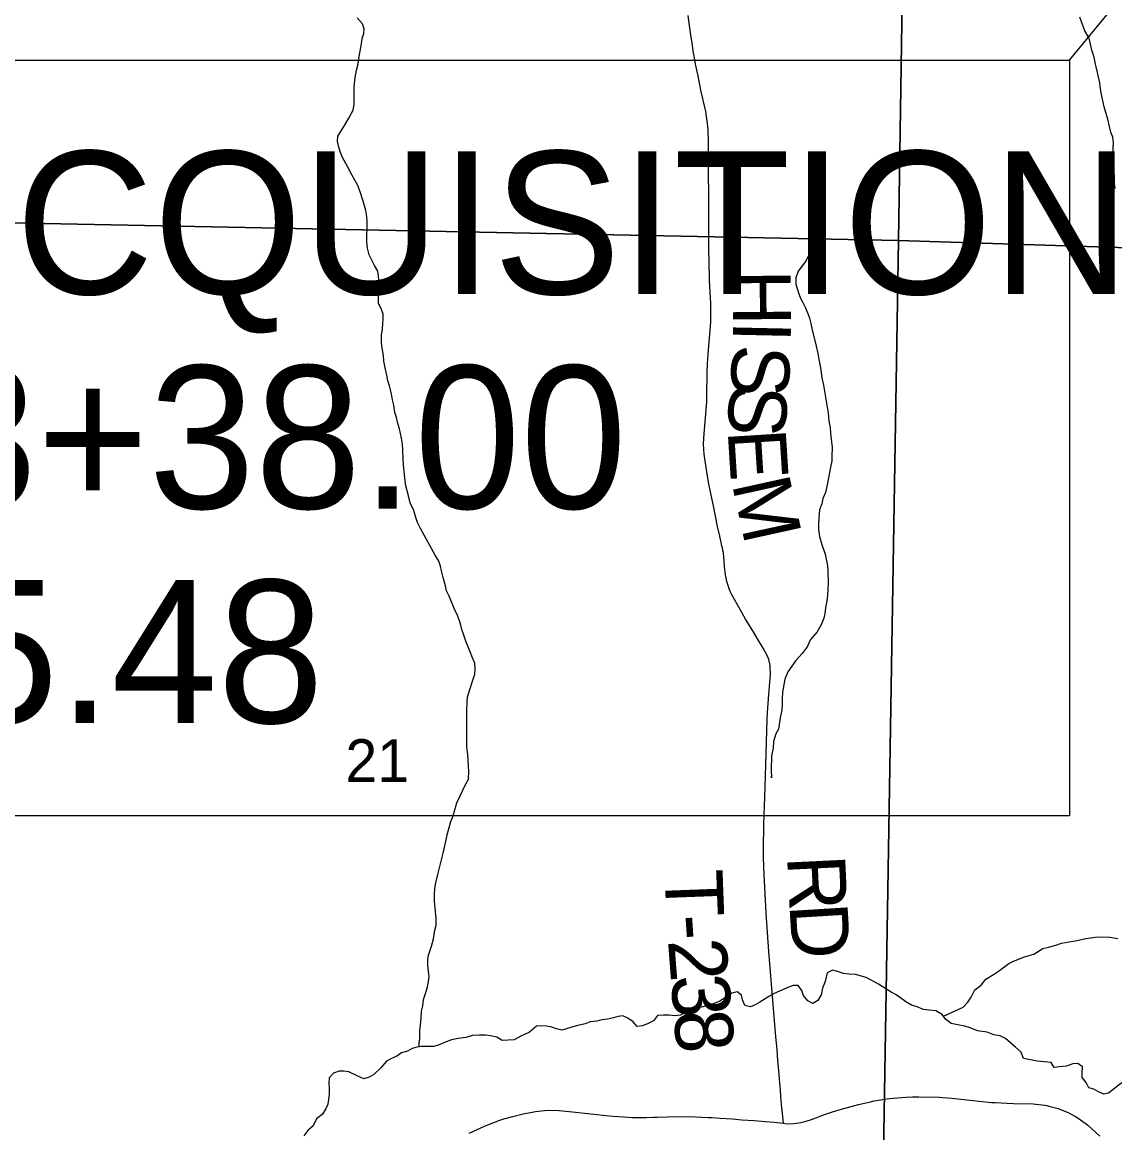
# Model space of a CAD drawing. Extents: x 0 to 34, y 0 to 22.
# Drawn here: x 11.571 to 12.641, y 15.132 to 16.22 of the extents above; entities that cross this region are included whole.
import ezdxf

# ---------------------------------------------------------------- set-up
doc = ezdxf.new("R2010")
doc.units = 0
for name, color, linetype in [('GM_X_Corporation', 7, 'Continuous'), ('GM_X_County_Road', 7, 'Continuous'), ('GM_X_Minor_River', 7, 'Continuous'), ('GM_X_Section_Text', 7, 'Continuous'), ('GM_X_Township_Road', 7, 'Continuous'), ('GM_X_Township_Road_Text', 7, 'Continuous'), ('SH_Text', 7, 'Continuous')]:
    doc.layers.add(name, color=color, linetype=linetype)

msp = doc.modelspace()

# ---------------------------------------------------------------- linework, layer by layer
at = {"layer": 'GM_X_Corporation'}
for points in [[(11.4395, 17.0255), (12.4446, 17.0089), (12.4291, 16.0062), (11.4274, 16.0262)], [(12.4446, 17.0089), (13.4493, 16.9912), (13.4336, 15.974), (12.4291, 16.0062)], [(11.4274, 16.0262), (12.4291, 16.0062), (12.4126, 14.9928), (11.4045, 15.0097)], [(12.4291, 16.0062), (13.4336, 15.974), (13.4208, 14.9679), (12.4126, 14.9928)]]:
    msp.add_lwpolyline(points, close=True, dxfattribs=at)
at = {"layer": 'GM_X_County_Road'}
msp.add_lwpolyline([(12.0086, 15.1317), (12.0114, 15.1331), (12.0235, 15.1387), (12.0267, 15.14), (12.0387, 15.1446), (12.0425, 15.1459), (12.0512, 15.1482), (12.0614, 15.1507), (12.0704, 15.1525), (12.0734, 15.153), (12.0823, 15.1541), (12.0853, 15.1542), (12.0966, 15.154), (12.1099, 15.1527), (12.1457, 15.1487), (12.1495, 15.1484), (12.1599, 15.1477), (12.1685, 15.1472), (12.1819, 15.1473), (12.1893, 15.1474), (12.1928, 15.1476), (12.2028, 15.1479), (12.2123, 15.1482), (12.2304, 15.1479), (12.243, 15.1473), (12.2466, 15.1471), (12.2545, 15.1465), (12.2664, 15.1457), (12.2757, 15.145), (12.2877, 15.1441), (12.2986, 15.1432), (12.3077, 15.1425), (12.3164, 15.1415), (12.3183, 15.1414), (12.3237, 15.1411), (12.3292, 15.1415), (12.3334, 15.1422), (12.3387, 15.1436), (12.3439, 15.1453), (12.3576, 15.1503), (12.3647, 15.1527), (12.372, 15.1549), (12.39, 15.1598), (12.4017, 15.1626), (12.4055, 15.1635), (12.4203, 15.1657), (12.4244, 15.1662), (12.4364, 15.1671), (12.4428, 15.1673), (12.449, 15.1675), (12.4694, 15.167), (12.4723, 15.1669), (12.4815, 15.1661), (12.4961, 15.1646), (12.5203, 15.1619), (12.5235, 15.1617), (12.542, 15.1609), (12.5611, 15.1605), (12.5637, 15.1602), (12.5726, 15.1591), (12.5745, 15.1589), (12.5767, 15.1584), (12.5856, 15.1559), (12.5879, 15.155), (12.5954, 15.1521), (12.5978, 15.1509), (12.6028, 15.1483), (12.6044, 15.1472), (12.6132, 15.141), (12.6147, 15.1398), (12.6266, 15.129)], dxfattribs=at)
at = {"layer": 'GM_X_Minor_River'}
for points in [[(11.9226, 15.9135), (11.9237, 15.9196), (11.9241, 15.9246), (11.9244, 15.9291), (11.9244, 15.9341), (11.9225, 15.9386), (11.9198, 15.9447), (11.9198, 15.9492), (11.9202, 15.9587), (11.9205, 15.9633), (11.9197, 15.9716), (11.919, 15.9762), (11.9159, 15.9815), (11.9106, 15.9921), (11.909, 15.9986), (11.9082, 16.0047), (11.9082, 16.01), (11.9086, 16.0191), (11.9086, 16.0244), (11.9082, 16.0297), (11.9074, 16.0354), (11.9047, 16.0445), (11.9016, 16.0537), (11.8993, 16.0601), (11.8936, 16.0704), (11.8894, 16.0787), (11.8844, 16.0874), (11.8825, 16.0924), (11.8806, 16.0984), (11.8794, 16.1034), (11.8798, 16.1083), (11.8855, 16.117), (11.8908, 16.1258), (11.8949, 16.1338), (11.896, 16.1395), (11.896, 16.1562), (11.8967, 16.1657), (11.8982, 16.1729), (11.8997, 16.1793), (11.9008, 16.1862), (11.903, 16.1987), (11.9038, 16.204), (11.9053, 16.209), (11.9056, 16.2135), (11.9041, 16.2185), (11.8988, 16.2242)], [(12.6416, 16.0571), (12.6408, 16.0624), (12.6408, 16.067), (12.6404, 16.0749), (12.64, 16.0799), (12.6396, 16.0909), (12.6395, 16.0962), (12.6399, 16.1023), (12.6391, 16.1072), (12.6372, 16.1121), (12.6361, 16.1178), (12.6345, 16.125), (12.6307, 16.1372), (12.6284, 16.1474), (12.6272, 16.1547), (12.6264, 16.1607), (12.6241, 16.1706), (12.6222, 16.1789), (12.621, 16.1858), (12.6187, 16.1926), (12.616, 16.2044), (12.6118, 16.2116), (12.6068, 16.2249)], [(12.3508, 16.0555), (12.3493, 16.0509), (12.3481, 16.0463), (12.347, 16.0403), (12.347, 16.0353), (12.3482, 16.03), (12.3497, 16.0236), (12.3497, 16.019), (12.3494, 16.0133), (12.3483, 16.0084), (12.3456, 16.0031), (12.3434, 15.9977), (12.3415, 15.992), (12.3388, 15.9867), (12.3351, 15.9818), (12.3309, 15.9761), (12.3287, 15.9696), (12.3287, 15.9635), (12.3314, 15.9548), (12.3329, 15.9502), (12.3356, 15.9453), (12.3379, 15.9408), (12.3405, 15.9347), (12.3421, 15.9301), (12.3432, 15.9248), (12.3448, 15.9187), (12.3486, 15.9028), (12.3502, 15.8956), (12.3513, 15.8895), (12.3529, 15.8815), (12.354, 15.8717), (12.3556, 15.8645), (12.3602, 15.8371), (12.361, 15.8295), (12.3622, 15.8231), (12.3626, 15.817), (12.3637, 15.809), (12.3641, 15.8033), (12.3638, 15.795), (12.3638, 15.7904), (12.3627, 15.784), (12.3608, 15.7737), (12.3593, 15.7669), (12.3578, 15.7593), (12.3552, 15.7536), (12.3541, 15.7482), (12.3518, 15.7422), (12.3507, 15.7293), (12.3507, 15.7232), (12.3519, 15.7163), (12.3542, 15.7084), (12.3573, 15.6989), (12.3584, 15.694), (12.3596, 15.6875), (12.36, 15.6822), (12.3604, 15.6708), (12.36, 15.6643), (12.3593, 15.6552), (12.3578, 15.6465), (12.3571, 15.6408), (12.356, 15.6362), (12.3533, 15.6298), (12.3496, 15.6229), (12.3431, 15.6153), (12.3397, 15.6081), (12.3348, 15.6016), (12.3288, 15.5948), (12.3246, 15.5891), (12.3208, 15.5838), (12.3178, 15.5765), (12.3156, 15.5636), (12.3152, 15.5572), (12.3152, 15.5515), (12.3149, 15.5465), (12.3134, 15.5385), (12.3115, 15.5275), (12.3089, 15.523), (12.3066, 15.5154), (12.3063, 15.5089), (12.3048, 15.5013), (12.3044, 15.4873), (12.3048, 15.48), (12.3047, 15.4816)], [(11.9594, 15.2164), (11.9594, 15.2197), (11.9602, 15.2246), (11.9601, 15.2326), (11.9609, 15.2375), (11.9616, 15.2444), (11.962, 15.2512), (11.9631, 15.2565), (11.9638, 15.2626), (11.9665, 15.2706), (11.9676, 15.2752), (11.9687, 15.2805), (11.9695, 15.2854), (11.9687, 15.2904), (11.9679, 15.2964), (11.9679, 15.3017), (11.9686, 15.3063), (11.9717, 15.315), (11.9735, 15.3223), (11.975, 15.3306), (11.9761, 15.3356), (11.9761, 15.3424), (11.9757, 15.3485), (11.9745, 15.3591), (11.9745, 15.3656), (11.9749, 15.3713), (11.976, 15.377), (11.9779, 15.3853), (11.9801, 15.3944), (11.9831, 15.4062), (11.985, 15.4146), (11.9872, 15.4252), (11.9906, 15.437), (11.9929, 15.4427), (11.9944, 15.4484), (11.9966, 15.4552), (11.9993, 15.4617), (12.0042, 15.472), (12.0079, 15.4784), (12.0083, 15.486), (12.0079, 15.4913), (12.0071, 15.5027), (12.0063, 15.51), (12.0063, 15.5191), (12.0062, 15.546), (12.0066, 15.554), (12.0069, 15.559), (12.0096, 15.5673), (12.0118, 15.5745), (12.0141, 15.5814), (12.0144, 15.5867), (12.014, 15.592), (12.0117, 15.5973), (12.0094, 15.6034), (12.0075, 15.6083), (12.0052, 15.6136), (12.0029, 15.6205), (12.0014, 15.625), (12.0002, 15.6307), (11.9972, 15.6391), (11.9945, 15.644), (11.9918, 15.6505), (11.9888, 15.6577), (11.9865, 15.663), (11.9853, 15.6679), (11.983, 15.6759), (11.9815, 15.6827), (11.9803, 15.6873), (11.9788, 15.6922), (11.9753, 15.6979), (11.97, 15.7074), (11.9665, 15.7139), (11.9608, 15.7241), (11.9578, 15.7298), (11.9562, 15.7347), (11.9543, 15.7416), (11.9509, 15.7491), (11.9493, 15.7548), (11.9466, 15.7659), (11.9455, 15.7734), (11.9443, 15.7867), (11.9439, 15.7917), (11.9435, 15.8008), (11.9431, 15.8065), (11.9423, 15.8126), (11.9404, 15.8217), (11.9388, 15.827), (11.9373, 15.8327), (11.9358, 15.8376), (11.9346, 15.8448), (11.9334, 15.8501), (11.9323, 15.8558), (11.9304, 15.8638), (11.9288, 15.8687), (11.928, 15.8741), (11.9261, 15.8813), (11.925, 15.8881), (11.9246, 15.8934), (11.923, 15.9025), (11.9226, 15.9071), (11.9226, 15.9135)], [(12.4732, 15.2465), (12.4927, 15.2551), (12.4973, 15.2601), (12.5003, 15.265), (12.5041, 15.2722), (12.5101, 15.2768), (12.5147, 15.2825), (12.5223, 15.2871), (12.5272, 15.2905), (12.5374, 15.2981), (12.542, 15.3004), (12.5526, 15.3046), (12.5617, 15.3073), (12.5708, 15.3126), (12.5761, 15.3141), (12.5833, 15.316), (12.589, 15.3179), (12.5962, 15.3191), (12.6026, 15.3203), (12.6129, 15.3225), (12.622, 15.3237), (12.6292, 15.3241), (12.6364, 15.3237), (12.644, 15.3226)], [(12.516, 15.2309), (12.5065, 15.232), (12.4993, 15.235), (12.4943, 15.2365), (12.4875, 15.238), (12.481, 15.2391), (12.4757, 15.2433), (12.4719, 15.2479), (12.4658, 15.2516), (12.459, 15.2524), (12.4536, 15.2531), (12.4476, 15.2554), (12.4419, 15.2573), (12.4365, 15.2603), (12.4316, 15.2641), (12.427, 15.2672), (12.4221, 15.2698), (12.4168, 15.2732), (12.4095, 15.2778), (12.4031, 15.2815), (12.3977, 15.2842), (12.3871, 15.2872), (12.381, 15.2876), (12.3753, 15.2883), (12.3696, 15.2902), (12.3647, 15.2914), (12.3594, 15.2887), (12.3575, 15.2803), (12.3549, 15.2739), (12.3534, 15.2674), (12.3503, 15.2617), (12.3454, 15.2587), (12.3405, 15.2613), (12.3363, 15.2666), (12.3344, 15.2716), (12.3309, 15.2765), (12.326, 15.2765), (12.3207, 15.2746), (12.3074, 15.2685), (12.3021, 15.2658), (12.2934, 15.2601), (12.2889, 15.2574), (12.2843, 15.2555), (12.2786, 15.257), (12.2763, 15.2623), (12.2755, 15.2669), (12.271, 15.2703), (12.266, 15.2688), (12.2588, 15.2642), (12.2543, 15.2612), (12.2471, 15.2581), (12.2418, 15.257), (12.2365, 15.2551), (12.2308, 15.2554), (12.2247, 15.2532), (12.2202, 15.2501), (12.2156, 15.2474), (12.2099, 15.2467), (12.2042, 15.2474), (12.1989, 15.2474), (12.1932, 15.247), (12.1891, 15.2417), (12.1834, 15.239), (12.1781, 15.2371), (12.1731, 15.2364), (12.1693, 15.2409), (12.164, 15.2443), (12.159, 15.2466), (12.1545, 15.2462), (12.1499, 15.2447), (12.1442, 15.2435), (12.1389, 15.2428), (12.1336, 15.2416), (12.1272, 15.2408), (12.1222, 15.2389), (12.115, 15.2374)], [(12.115, 15.2374), (12.1093, 15.2355), (12.104, 15.234), (12.0995, 15.2328), (12.0942, 15.234), (12.0896, 15.2355), (12.0843, 15.2366), (12.0793, 15.237), (12.0744, 15.2366), (12.0676, 15.2309), (12.0593, 15.2267), (12.0528, 15.2233), (12.0467, 15.2229), (12.041, 15.2225), (12.0357, 15.2259), (12.0296, 15.227), (12.0247, 15.2278), (12.0186, 15.2278), (12.0118, 15.2274), (12.0053, 15.2255), (11.9978, 15.2247), (11.9913, 15.2232), (11.9845, 15.2205), (11.9792, 15.2182), (11.9739, 15.2167), (11.9617, 15.2167), (11.9572, 15.2159), (11.9526, 15.2147), (11.9481, 15.2121), (11.9424, 15.2105), (11.9378, 15.2071), (11.9325, 15.2048), (11.9276, 15.2022), (11.9219, 15.1957), (11.9151, 15.1892), (11.9106, 15.1866), (11.9052, 15.185), (11.8995, 15.1877), (11.8908, 15.1919), (11.8859, 15.1926), (11.8813, 15.1926), (11.8756, 15.1907), (11.8715, 15.1861), (11.8711, 15.1808), (11.8715, 15.1755), (11.8715, 15.1705), (11.8708, 15.1648), (11.87, 15.1603), (11.8681, 15.1557), (11.8644, 15.15), (11.859, 15.1458), (11.8557, 15.139), (11.8504, 15.1344), (11.8466, 15.1291)], [(12.6156, 15.1763), (12.613, 15.1816), (12.6092, 15.1862), (12.6091, 15.1907), (12.6095, 15.1968), (12.6049, 15.2002), (12.6, 15.1998), (12.5935, 15.1975), (12.5871, 15.1968), (12.5818, 15.196), (12.5787, 15.2009), (12.5723, 15.2017), (12.5651, 15.2024), (12.5571, 15.2039), (12.5518, 15.2051), (12.5495, 15.2111), (12.5438, 15.2161), (12.5342, 15.2244), (12.5289, 15.2271), (12.5228, 15.2282), (12.516, 15.2309)], [(12.7092, 15.1301), (12.7035, 15.1347), (12.6981, 15.1388), (12.6932, 15.1392), (12.6887, 15.1385), (12.6822, 15.1381), (12.6784, 15.1426), (12.6734, 15.1502), (12.6708, 15.1548), (12.6662, 15.1578), (12.6628, 15.1623), (12.6616, 15.1673), (12.6604, 15.1726), (12.6604, 15.1771), (12.657, 15.1825), (12.6509, 15.1832), (12.6456, 15.179), (12.635, 15.171), (12.6305, 15.1699), (12.6251, 15.1722), (12.6206, 15.1748), (12.6156, 15.1763)]]:
    msp.add_lwpolyline(points, dxfattribs=at)
at = {"layer": 'GM_X_Township_Road'}
msp.add_lwpolyline([(12.3164, 15.1415), (12.3155, 15.151), (12.3147, 15.1598), (12.3141, 15.1677), (12.3136, 15.174), (12.313, 15.1812), (12.3123, 15.1888), (12.3117, 15.1963), (12.3111, 15.2028), (12.3102, 15.2137), (12.3091, 15.2262), (12.3023, 15.3099), (12.3002, 15.3378), (12.2996, 15.3475), (12.2977, 15.385), (12.2971, 15.4014), (12.2969, 15.4102), (12.2972, 15.4342), (12.2982, 15.461), (12.2992, 15.4925), (12.3006, 15.5374), (12.3009, 15.5439), (12.3022, 15.5614), (12.3039, 15.5809), (12.3036, 15.5885), (12.3034, 15.5903), (12.3022, 15.5956), (12.3015, 15.5974), (12.2998, 15.6011), (12.2967, 15.6069), (12.2921, 15.6145), (12.2864, 15.6237), (12.2794, 15.6354), (12.274, 15.6446), (12.2659, 15.6591), (12.2649, 15.6612), (12.2634, 15.6648), (12.2623, 15.6682), (12.2611, 15.6722), (12.2603, 15.6756), (12.2598, 15.6788), (12.2589, 15.6873), (12.2581, 15.6965), (12.2578, 15.6994), (12.2576, 15.7007), (12.2574, 15.7016), (12.2572, 15.7025), (12.257, 15.7034), (12.2562, 15.7071), (12.2555, 15.7102), (12.2541, 15.7167), (12.252, 15.726), (12.2498, 15.7362), (12.2478, 15.7461), (12.2454, 15.7582), (12.2435, 15.7678), (12.2418, 15.7774), (12.2408, 15.7839), (12.2389, 15.797), (12.2385, 15.8013), (12.2382, 15.8072), (12.2388, 15.8171), (12.2402, 15.8323), (12.2409, 15.8407), (12.2413, 15.8482), (12.2415, 15.8536), (12.2416, 15.877), (12.242, 15.8853), (12.2432, 15.899), (12.2451, 15.9219), (12.2454, 15.9272), (12.2453, 15.9447), (12.245, 15.9501), (12.2442, 15.967), (12.2438, 15.9861), (12.2434, 15.9963), (12.2435, 16.0232), (12.2432, 16.0991), (12.2431, 16.106), (12.2429, 16.1118), (12.2428, 16.1147), (12.2425, 16.1181), (12.2422, 16.1207), (12.2419, 16.1231), (12.2412, 16.1276), (12.2403, 16.1326), (12.2357, 16.1534), (12.2328, 16.1673), (12.2304, 16.179), (12.2292, 16.1852), (12.2281, 16.1915), (12.2269, 16.1996), (12.2258, 16.2072), (12.2245, 16.2167), (12.2233, 16.2266)], dxfattribs=at)
at = {"layer": 'SH_Text'}
msp.add_line((12.5969, 16.1826), (13.1775, 16.8923), dxfattribs=at)
msp.add_lwpolyline([(10.7649, 16.1826), (12.5969, 16.1826), (12.5969, 15.4427), (10.7649, 15.4427)], close=True, dxfattribs=at)

# ---------------------------------------------------------------- texts
at = {"layer": 'GM_X_Section_Text'}
msp.add_text('21', height=0.04186, rotation=0, dxfattribs=at).set_placement((11.8873, 15.4758))
at = {"layer": 'GM_X_Township_Road_Text'}
for s, rotation, p in [('H', 270.4954, (12.2668, 15.9775)), ('I', 268.7665, (12.2672, 15.928)), ('S', 267.4619, (12.2667, 15.905)), ('S', 265.2383, (12.265, 15.8673)), ('E', 273.6204, (12.2618, 15.82)), ('M', 282.4155, (12.2658, 15.7682)), ('R', 272.7644, (12.32, 15.4031)), ('T', 272.1433, (12.2, 15.3889)), ('D', 273.5028, (12.3223, 15.3557)), ('-', 273.9077, (12.2017, 15.3445)), ('2', 274.3653, (12.2033, 15.3208)), ('3', 274.6738, (12.206, 15.2855)), ('8', 274.7356, (12.2088, 15.2506))]:
    msp.add_text(s, height=0.0568, rotation=rotation, dxfattribs=at).set_placement(p)
at = {"layer": 'SH_Text'}
for s, p in [('BEGIN ACQUISITION', (10.8047, 15.9536)), ('STA. 823+38.00', (10.8047, 15.7436)), ('S.L.M. 15.48', (10.8047, 15.5336))]:
    msp.add_text(s, height=0.14, dxfattribs=at).set_placement(p)

doc.saveas('drawing.dxf')
